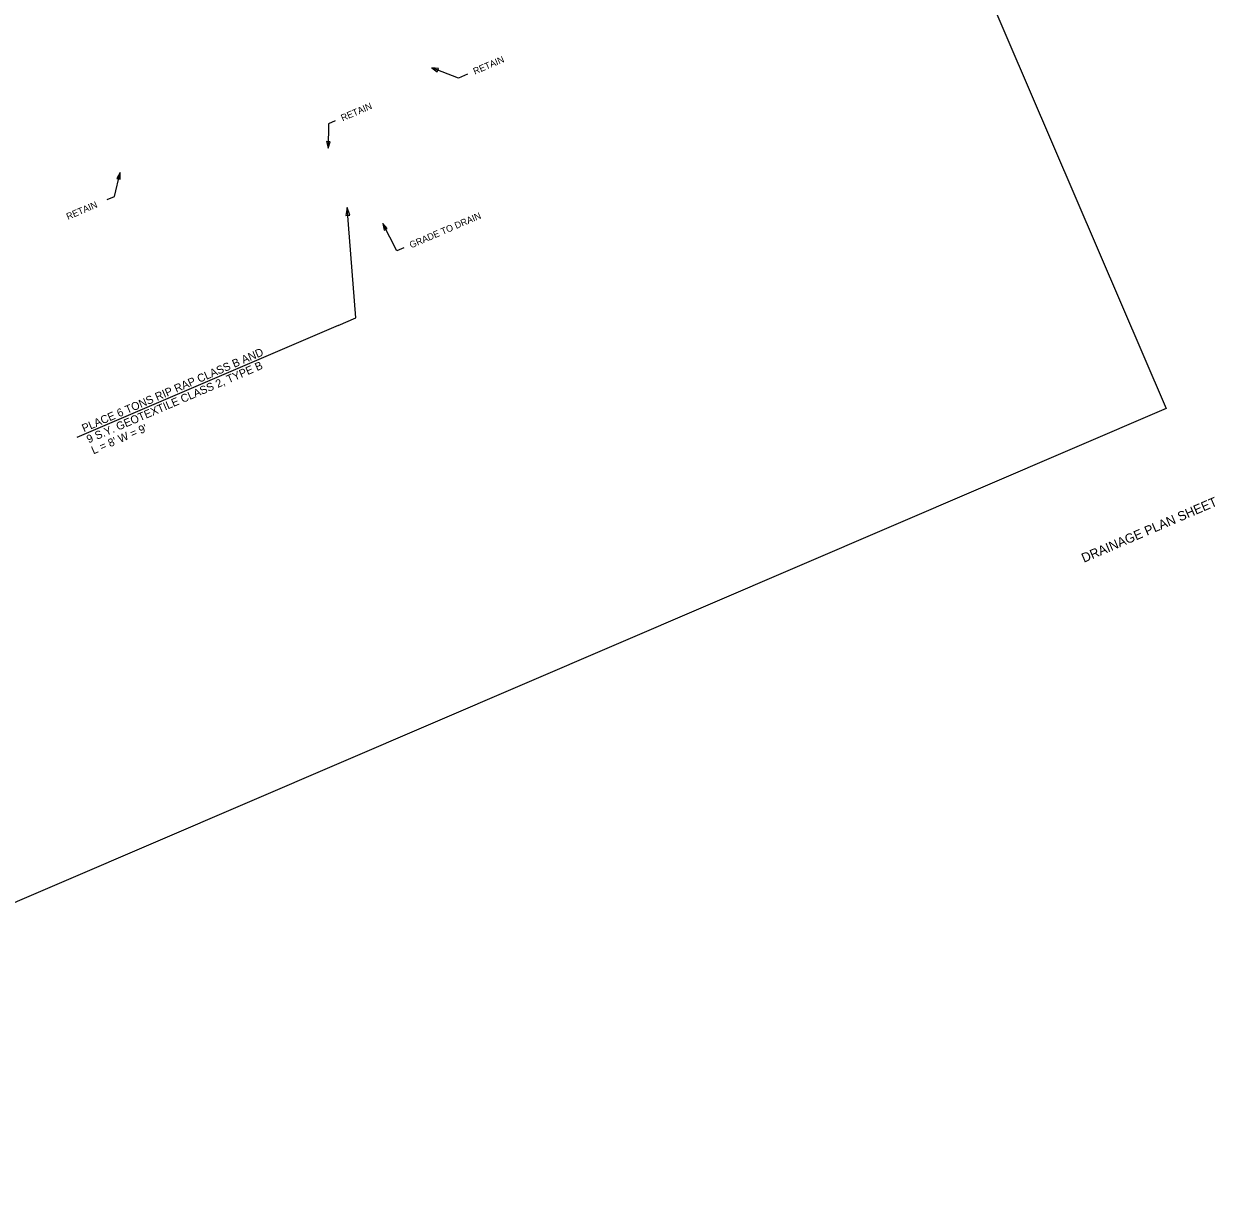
# Model space of a CAD drawing. Extents: x 1618261 to 1620114, y 1101131 to 1103031.
# Drawn here: x 1619221 to 1620114, y 1101201 to 1102081 of the extents above; entities that cross this region are included whole.
import ezdxf

# ---------------------------------------------------------------- set-up
doc = ezdxf.new("R2010")
doc.units = 0
for name, color, linetype in [('Level 2', 7, 'Continuous'), ('Level 20', 7, 'Continuous'), ('RFP', 7, 'Continuous')]:
    doc.layers.add(name, color=color, linetype=linetype)

msp = doc.modelspace()

# ---------------------------------------------------------------- linework, layer by layer
at = {"layer": 'Level 2'}
msp.add_line((1619456.41, 1101854.81), (1619260.56, 1101770.75), dxfattribs=at)
for points in [[(1619553.42, 1102043.28), (1619546.72, 1102040.4), (1619526.78, 1102048.06)], [(1619454.31, 1102008.3), (1619449.39, 1102006.19), (1619449.07, 1101987.88)], [(1619283.26, 1101949.28), (1619288.75, 1101951.64), (1619292.96, 1101969.51)], [(1619456.41, 1101854.81), (1619469.73, 1101860.53), (1619463.32, 1101943.23)], [(1619505.7, 1101912.98), (1619500.49, 1101910.75), (1619489.97, 1101931.27)]]:
    msp.add_lwpolyline(points, dxfattribs=at)
for points in [[(1619531.75, 1102047.54), (1619526.78, 1102048.06), (1619530.82, 1102045.12)], [(1619447.86, 1101992.73), (1619449.07, 1101987.88), (1619450.45, 1101992.68)], [(1619293.12, 1101964.52), (1619292.96, 1101969.51), (1619290.6, 1101965.11)], [(1619465.32, 1101937.57), (1619463.32, 1101943.23), (1619462.22, 1101937.33)], [(1619493.32, 1101927.56), (1619489.97, 1101931.27), (1619491.02, 1101926.38)]]:
    msp.add_lwpolyline(points, close=True, dxfattribs=at)
at = {"layer": 'RFP'}
msp.add_lwpolyline([(1618327.62, 1102066.11), (1619552.64, 1102591.88), (1619565.97, 1102561.62), (1619719.68, 1102625.9), (1620077.33, 1101792.57), (1618698.92, 1101200.97)], close=True, dxfattribs=at)
msp.add_lwpolyline([(1618327.62, 1102066.11), (1619552.64, 1102591.88), (1619565.97, 1102561.62), (1619719.68, 1102625.9), (1620077.33, 1101792.57), (1618698.92, 1101200.97)], close=True, dxfattribs=at)
msp.add_lwpolyline([(1618327.62, 1102066.11), (1619552.64, 1102591.88), (1619565.97, 1102561.62), (1619719.68, 1102625.9), (1620077.33, 1101792.57), (1618698.92, 1101200.97)], close=True, dxfattribs=at)
msp.add_lwpolyline([(1618327.62, 1102066.11), (1619552.64, 1102591.88), (1619565.97, 1102561.62), (1619719.68, 1102625.9), (1620077.33, 1101792.57), (1618698.92, 1101200.97)], close=True, dxfattribs=at)
msp.add_lwpolyline([(1618327.62, 1102066.11), (1619552.64, 1102591.88), (1619565.97, 1102561.62), (1619719.68, 1102625.9), (1620077.33, 1101792.57), (1618698.92, 1101200.97)], close=True, dxfattribs=at)

# ---------------------------------------------------------------- texts
at = {"layer": 'Level 2'}
for s, height, rotation, p in [('RETAIN', 5, 23.22835, (1619559, 1102042.95)), ('RETAIN', 5, 23.22835, (1619459.89, 1102007.98)), ('RETAIN', 5, 23.23096, (1619253.97, 1101933.99)), ('GRADE TO DRAIN', 5, 23.22835, (1619511.28, 1101912.66)), ('PLACE 6 TONS RIP RAP CLASS B AND', 6, 23.22835, (1619265.9, 1101774.68)), ('9 S.Y. GEOTEXTILE CLASS 2, TYPE B', 6, 23.22835, (1619269.45, 1101766.41)), ("L = 8' W = 9'", 6, 23.22835, (1619273, 1101758.14))]:
    msp.add_text(s, height=height, rotation=rotation, dxfattribs=at).set_placement(p)
at = {"layer": 'Level 20'}
msp.add_text('DRAINAGE PLAN SHEET', height=6.9833, rotation=23.22835, dxfattribs=at).set_placement((1620015.66, 1101676.82))

doc.saveas('drawing.dxf')
